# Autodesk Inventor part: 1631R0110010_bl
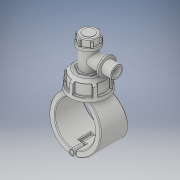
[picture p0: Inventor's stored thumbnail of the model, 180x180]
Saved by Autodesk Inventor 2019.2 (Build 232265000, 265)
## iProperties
Created: 2022-02
Part Number: 1631R0110010_bl
Material: Generic
Description: Plassadle Tapper Male 110x1''
Document SubType Name: Modeling
Designer: comp2
Density: 1 g/cm^3
Appearance: Default
Author: comp2
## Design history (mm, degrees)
derived "1631R.ipt"
feature "Solid1::1631R.ipt" dims "ScaleForDerivedMember" = 10
feature "Solid2::1631R.ipt" dims "ScaleForDerivedMember" = 10
feature "Solid3::1631R.ipt" dims "ScaleForDerivedMember" = 10
feature "Solid4::1631R.ipt" dims "ScaleForDerivedMember" = 10
tag "TaggingFeature1"
body "Solid1"
body "Solid2"
body "Solid3"
body "Solid4"
other parameters: "d2" = 141 [user parameter], "d3" = 55 [user parameter], "d5" = 273 [user parameter], "d7" = 133.95 [user parameter], "d8" = 85 deg [user parameter], "d9" = 45 deg [user parameter], "d10" = 102 [user parameter], "d11" = 49 [user parameter], "d12" = 34.3 [user parameter], "d13" = 42.84 [user parameter], "d14" = 57.936 [user parameter], "d15" = 2.45 [user parameter], "d16" = 2 [user parameter], "d17" = 2 [user parameter], "d18" = 29.4 [user parameter], "d19" = 7.35 [user parameter], "d20" = 1 [user parameter], "d21" = 30.6 [user parameter], "d22" = 1 [user parameter], "d23" = 14.7 [user parameter], "d24" = 78 [user parameter], "d27" = 144 [user parameter], "d29" = 49.8735 [user parameter], "d31" = 33.249 [user parameter], "d32" = 31.2 [user parameter], "d33" = 26.52 [user parameter], "d41" = 5 [user parameter], "d42" = 3.1 [user parameter], "d46" = 56.1 [user parameter], "d47" = 36.5739 [user parameter], "d48" = 49 [user parameter], "d49" = 2.82 [user parameter], "d50" = 97 [user parameter], "d51" = 0 [user parameter], "d52" = 21.7 [user parameter], "d53" = 77.55 [user parameter], "d54" = 33.95 [user parameter], "d55" = 0 [user parameter], "d56" = 19.4 [user parameter], "d57" = 19.4 [user parameter], "d59" = 0 [user parameter], "d60" = 97 [user parameter], "d61" = 0 [user parameter], "d62" = 33.95 [user parameter], "d63" = 0 [user parameter], "d65" = 0 [user parameter], "d67" = 0 [user parameter], "d69" = 0 [user parameter], "d70" = 1 [user parameter], "d71" = 93.12 [user parameter], "d72" = 0 [user parameter], "d73" = 2 [user parameter], "d77" = 24.93675 [user parameter], "d78" = 86.7 [user parameter], "d79" = 5.1 [user parameter], "d80" = 60 deg [user parameter], "d81" = 5.1 [user parameter], "d84" = 0 [user parameter], "d85" = 1 [user parameter], "d87" = 360 deg [user parameter], "d90" = 0 [user parameter], "d91" = 1 [user parameter], "d93" = 60 deg [user parameter], "d94" = 3.06 [user parameter], "d95" = 3.06 [user parameter], "d97" = 0 [user parameter], "d98" = 0.5 [user parameter], "d100" = 360 deg [user parameter], "d102" = 2 [user parameter], "d117" = 0.5 [user parameter], "d118" = 31.2 [user parameter], "d119" = 100 deg [user parameter], "d121" = 0 [user parameter], "d1" = 25 [user parameter], "B" = 141 [user parameter], "L" = 97 [user parameter], "E_" = 54 [user parameter], "E1" = 102 [user parameter], "H1" = 273 [user parameter], "H2" = 144 [user parameter], "H3" = 78 [user parameter], "H_costum" = 49 [user parameter], "R" = 33.249 [user parameter]
